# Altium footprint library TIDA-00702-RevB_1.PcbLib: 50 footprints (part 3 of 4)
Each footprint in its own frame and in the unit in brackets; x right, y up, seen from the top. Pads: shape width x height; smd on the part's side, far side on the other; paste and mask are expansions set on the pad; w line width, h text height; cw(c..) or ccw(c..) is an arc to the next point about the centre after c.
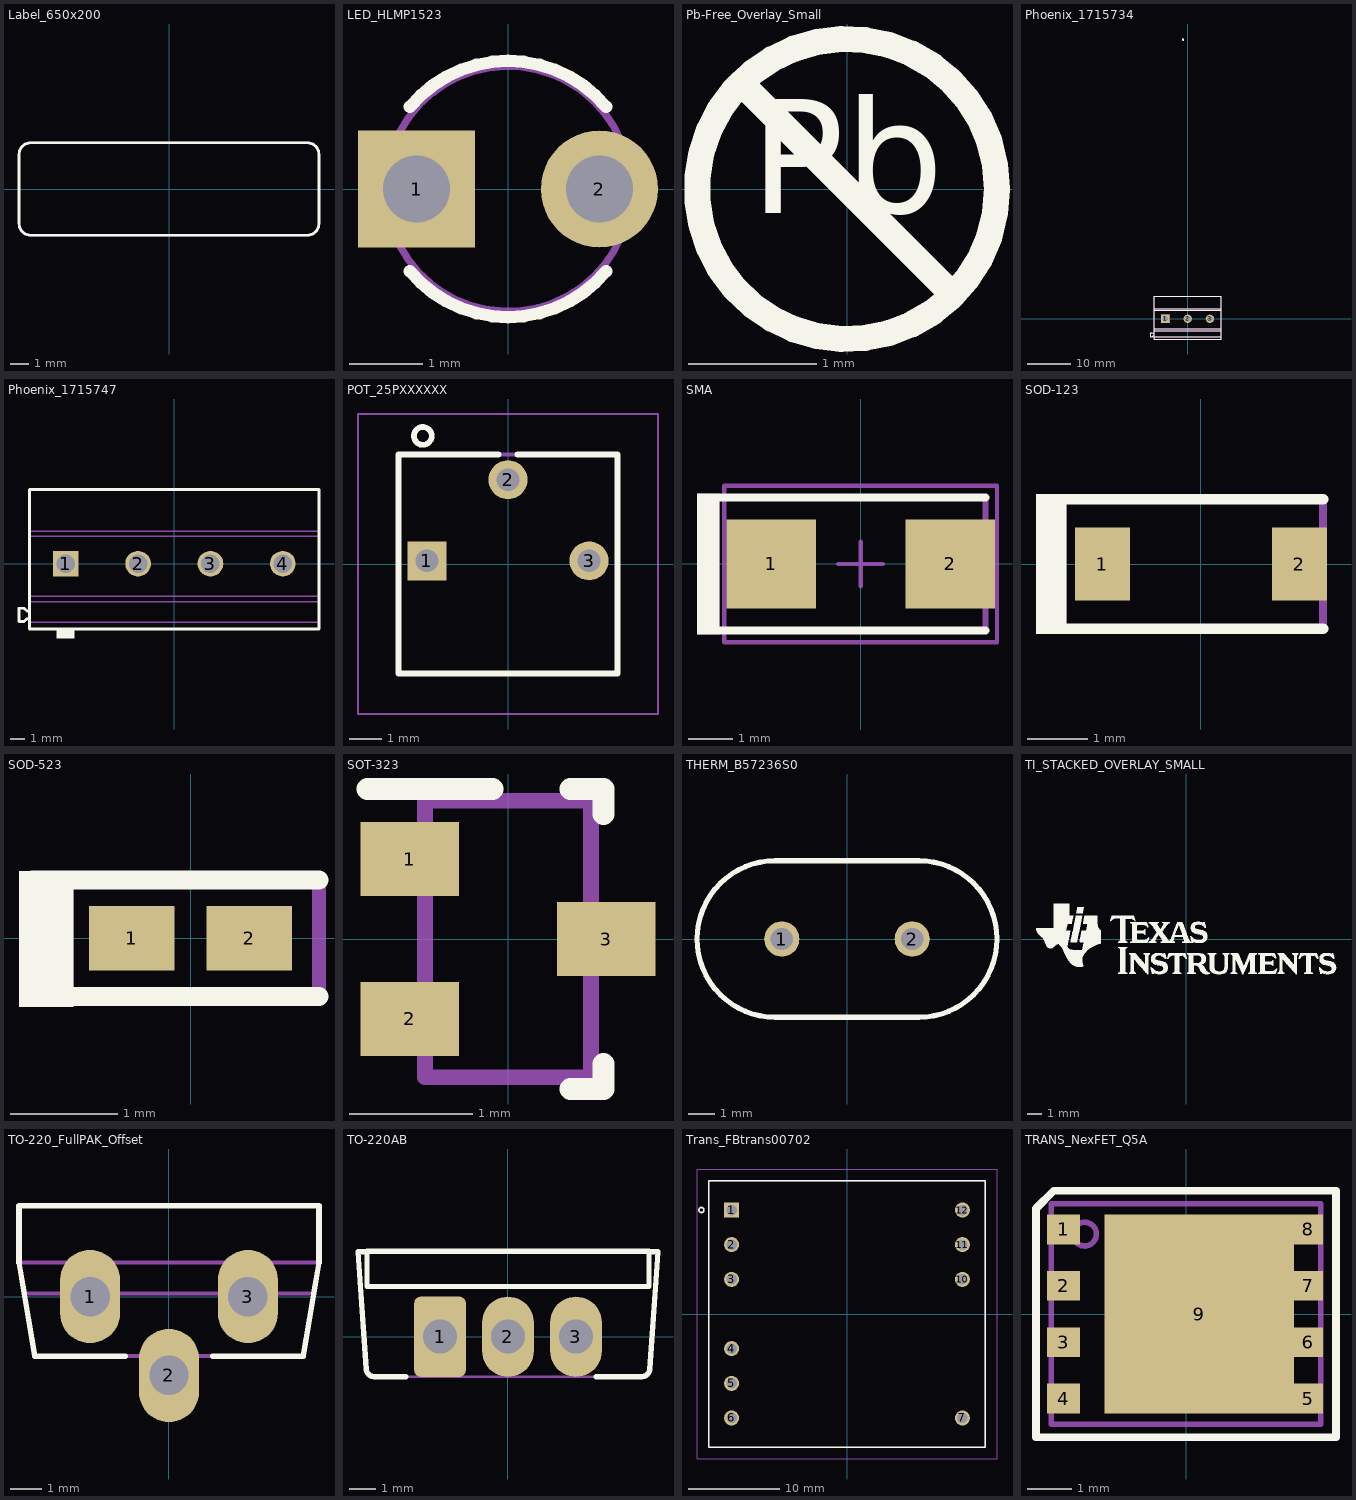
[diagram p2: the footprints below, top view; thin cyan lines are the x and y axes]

## Label_650x200 [mm] "Thermal Transfer Label"
height 0.025
Top Overlay:
  lines w0.152: -8.255,-1.905 ccw(c-7.62,-1.905) -7.62,-2.54 7.62,-2.54 ccw(c7.62,-1.905) 8.255,-1.905 8.255,1.905 ccw(c7.62,1.905) 7.62,2.54 -7.62,2.54 ccw(c-7.62,1.905) -8.255,1.905 -8.255,-1.905
Mechanical 5:
  lines w0.127: -8.255,-1.905 ccw(c-7.62,-1.905) -7.62,-2.54 7.62,-2.54 ccw(c7.62,-1.905) 8.255,-1.905 8.255,1.905 ccw(c7.62,1.905) 7.62,2.54 -7.62,2.54 ccw(c-7.62,1.905) -8.255,1.905 -8.255,-1.905
  text ".Designator" at -1.524,-0.508 h0.89
3D body: height 0.03, standoff 0, extent -8.268,-2.553 8.268,2.553

## LED_HLMP1523 [mm] "Everlight Electronics"
height 4.8
pads (2):
  rect 1.6x1.6 hole 0.914: 1(-1.25,0)
  round 1.6 hole 0.914: 2(1.25,0)
Top Overlay:
  lines w0.17: -1.341,-1.125 ccw(c0,0) 1.341,-1.125 ; -1.341,1.125 cw(c0,0) 1.341,1.125
Mechanical 5:
  lines w0.1: -1.57,-0.571 ccw(c0.004,0.002) -1.57,0.575 -1.57,-0.571
  text ".Designator" at 0.305,-0.635 h0.89
3D body: height 6.2, standoff -4.86, extent -1.6,-1.675 1.675,1.675

## Pb-Free_Overlay_Small [mm]
Top Overlay:
  circle w0.203: c0,0 r1.168
  lines w0.203: -0.826,0.826 0.826,-0.826
  text "Pb" at -0.752,-0.48 h1.52

## Phoenix_1715734 [mm] "Phoenix"
height 13.8
pads (3):
  rect 1.9x1.9 hole 1.321: 1(-5.08,0)
  round 1.9 hole 1.321: 2(0,0) 3(5.08,0)
Top Overlay:
  circle w0.152: c-1.033,63.678 r0.152
  lines w0.2: -7.62,-3.869 -7.787,-3.869 -8.019,-4.064 -8.361,-4.064 -8.361,-3.136 -8.019,-3.136 -7.787,-3.331 -7.62,-3.331 ; -7.62,-4.1 7.62,-4.1 ; -7.62,-4.1 -7.62,-4.6 7.62,-4.6 7.62,-4.1 ; -7.62,-4.1 -7.62,-2.672 ; -7.62,-2.672 7.62,-2.672 ; -7.62,-2.672 -7.62,-2.283 ; -7.62,-2.283 7.62,-2.283 ; -7.62,-2.283 -7.62,1.909 ; -7.62,1.909 7.62,1.909 ; -7.62,1.909 -7.62,2.29 ; -7.62,2.29 7.62,2.29 ; -7.62,2.29 -7.62,5.2 7.62,5.2 7.62,2.29 ; 7.62,-4.1 7.62,-2.672 ; 7.62,-2.672 7.62,-2.283 ; 7.62,-2.283 7.62,1.909 ; 7.62,1.909 7.62,2.29
Mechanical 5:
  region: -6.025,0.95 -4.125,0.95 -4.125,-0.95 -6.025,-0.95
  lines w0.127: -7.62,-3.869 -7.787,-3.869 -8.019,-4.064 -8.361,-4.064 -8.361,-3.136 -8.019,-3.136 -7.787,-3.331 -7.62,-3.331 ; -7.62,-4.1 -7.62,-2.672 ; -7.62,-4.1 -7.62,-4.6 7.62,-4.6 7.62,-4.1 ; -7.62,-4.1 7.62,-4.1 ; -7.62,-2.672 -7.62,-2.283 ; -7.62,-2.672 7.62,-2.672 ; -7.62,-2.283 -7.62,1.909 ; -7.62,-2.283 7.62,-2.283 ; -7.62,1.909 -7.62,2.29 ; -7.62,1.909 7.62,1.909 ; -7.62,2.29 -7.62,5.2 7.62,5.2 7.62,2.29 ; -7.62,2.29 7.62,2.29 ; 7.62,-4.1 7.62,-2.672 ; 7.62,-2.672 7.62,-2.283 ; 7.62,-2.283 7.62,1.909 ; 7.62,1.909 7.62,2.29
  text ".Designator" at -2.21,0.33 h0.89
3D body: height 14.2, standoff -3.5, extent -8.361,-4.6 7.62,5.2

## Phoenix_1715747 [mm] "Terminal Block, 5.08mm, 4x1, TH"
height 13.8
pads (4):
  rect 1.8x1.8 hole 1.3: 1(-7.62,0)
  round 1.8 hole 1.3: 2(-2.54,0) 3(2.54,0) 4(7.62,0)
Top Overlay:
  rectangle: -8.255,-5.25 -7.005,-4.599
  lines w0.2: -10.16,-3.869 -10.327,-3.869 -10.559,-4.064 -10.901,-4.064 -10.901,-3.136 -10.559,-3.136 -10.327,-3.331 -10.16,-3.331 ; -10.16,-4.6 10.16,-4.6 10.16,5.2 -10.16,5.2 -10.16,-4.6
Mechanical 5:
  lines w0.1: -10.16,-4.1 10.16,-4.1 ; -10.16,-3.869 -10.327,-3.869 -10.559,-4.064 -10.901,-4.064 -10.901,-3.136 -10.559,-3.136 -10.327,-3.331 -10.16,-3.331 ; -10.16,-2.672 10.16,-2.672 ; -10.16,-2.283 10.16,-2.283 ; -10.16,1.909 10.16,1.909 ; -10.16,2.29 10.16,2.29 ; -10.16,-4.6 -10.16,5.2 10.16,5.2 10.16,-4.6 -10.16,-4.6
  text ".Designator" at -0.559,0.66 h0.89
3D body: height 14.2, standoff -3.5, extent -10.901,-4.6 10.16,5.2

## POT_25PXXXXXX [mm] "Potentiometer, 25p series, through hole, 3 pin"
height 5.13
pads (3):
  rect 1.222x1.222 hole 0.714: 1(-2.54,0.1)
  round 1.222 hole 0.714: 2(0,2.64) 3(2.54,0.1)
Top Overlay:
  circle w0.178: c-2.667,4.013 r0.279
  lines w0.178: -0.3,3.43 -3.43,3.43 -3.43,-3.43 3.43,-3.43 3.43,3.43 0.3,3.43
  text ".Designator" at 3.708,0.737 h0.89
Mechanical 5:
  circle w0.127: c-2.54,0.1 r0.279
  lines w0.127: -3.43,-3.43 3.43,-3.43 3.43,3.43 -3.43,3.43 -3.43,-3.43
  text ".Designator" at -0.178,1.295 h0.89
Mechanical 15:
  lines w0.05: -4.7,-4.7 4.7,-4.7 4.7,4.7 -4.7,4.7 -4.7,-4.7
Mechanical 17:
  text "Lead Length : 5.08  +/- 1.01mm" at -12.954,1.778 h1.02
3D body: height 5.13, standoff 0, extent -3.43,-3.43 3.43,3.43

## SMA [mm] "Molded Diode, 2-Leads, Body 4.3x2.6mm, IPC Medium Density, based on OnSemi component dimensions and land pattern"
height 2.27
pads (2):
  rect 2x2 smd: 1(-2,0) 2(2,0)
Top Overlay:
  rectangle: -3.658,-1.575 -3.15,1.575
  lines w0.178: -3.327,-1.486 2.794,-1.486 ; -3.327,1.486 2.794,1.486
Mechanical 5:
  rectangle: -3.658,-1.575 -3.15,1.575
  lines w0.127: -3.327,-1.486 2.794,-1.486 2.794,1.486 -3.327,1.486
  text ".Designator" at -2.769,-0.33 h0.89
Mechanical 15:
  lines w0.1: -0.5,0 0.5,0 ; 0,-0.5 0,0.5 ; -3.05,-1.75 3.05,-1.75 3.05,1.75 -3.05,1.75 -3.05,-1.75
3D body: height 2.42, standoff 0.02, extent -2.6,-1.3 2.6,1.3

## SOD-123 [mm] "On Semi recommended land pattern"
height 1.35
pads (2):
  rect 0.915x1.22 smd: 1(-1.637,0) 2(1.637,0)
Top Overlay:
  rectangle: -2.743,-1.168 -2.235,1.168
  lines w0.178: -2.413,-1.079 2.032,-1.079 ; -2.413,1.079 2.032,1.079
Mechanical 5:
  rectangle: -2.743,-1.168 -2.235,1.168
  lines w0.127: -2.413,-1.079 2.032,-1.079 2.032,1.079 -2.413,1.079
  text ".Designator" at -1.956,-0.33 h0.89
3D body: height 1.35, standoff 0, extent -1.932,-0.9 1.932,0.9

## SOD-523 [mm] "NXP Semiconductor recommended land pattern, nominal STEP model"
height 0.7
pads (2):
  rect 0.8x0.6 smd paste-0.05: 1(-0.55,0) 2(0.55,0)
Top Overlay:
  rectangle: -1.602,-0.642 -1.094,0.628
  lines w0.178: -1.475,-0.546 0,-0.546 1.2,-0.546 ; -1.475,0.546 0,0.546 1.2,0.546
Mechanical 5:
  rectangle: -1.602,-0.642 -1.094,0.628
  lines w0.127: -1.475,-0.546 0,-0.546 1.2,-0.546 1.2,0.546 0,0.546 -1.475,0.546
  text ".Designator" at 2.972,0.375 h0.89
3D body: height 0.72, standoff 0.02, extent -0.8,-0.399 0.8,0.399

## SOT-323 [mm] "Zetex recommended land pattern.  March 2007"
height 1.1
pads (3):
  rect 0.8x0.6 smd: 1(-0.8,0.65) 2(-0.8,-0.65) 3(0.8,0)
Top Overlay:
  lines w0.178: -1.143,1.219 -0.127,1.219 ; 0.508,-1.219 0.775,-1.219 0.775,-1.016 ; 0.508,1.219 0.775,1.219 0.775,1.016
Mechanical 5:
  lines w0.127: -1.125,-0.8 -0.975,-0.8 -0.935,-0.8 -0.884,-0.8 -0.725,-0.8 -0.675,-0.8 -0.675,-0.5 -0.725,-0.5 -0.884,-0.5 -0.935,-0.5 -0.975,-0.5 -1.125,-0.5 -1.125,-0.8 ; -1.125,0.5 -0.975,0.5 -0.935,0.5 -0.884,0.5 -0.725,0.5 -0.675,0.5 -0.675,0.8 -0.725,0.8 -0.884,0.8 -0.935,0.8 -0.975,0.8 -1.125,0.8 -1.125,0.5 ; -0.675,-1.125 0.675,-1.125 0.675,1.125 -0.675,1.125 -0.675,-1.125 ; 0.675,-0.15 0.675,0.15 0.725,0.15 0.884,0.15 0.935,0.15 0.975,0.15 1.125,0.15 1.125,-0.15 0.975,-0.15 0.935,-0.15 0.884,-0.15 0.725,-0.15 0.675,-0.15
  text ".Designator" at 0.47,-0.645 h0.89
3D body: height 1.13, standoff 0.02, extent -1.125,-1.125 1.125,1.125

## THERM_B57236S0 [mm] "EPCOS"
height 16
pads (2):
  round 1.35 hole 0.85: 1(-2.5,0) 2(2.5,0)
Top Overlay:
  lines w0.2: -2.75,-3 cw(c-2.75,0) -2.75,3 2.75,3 cw(c2.75,0) 2.75,-3 -2.75,-3
Mechanical 5:
  lines w0.1: -2.75,-3 cw(c-2.75,0) -2.75,3 2.75,3 cw(c2.75,0) 2.75,-3 -2.75,-3
  text ".Designator" at -0.864,0.178 h0.89
3D body: height 15.99, standoff 4.51, extent -5.755,-3 5.7,3
3D body: height 5.5, standoff -2.5, extent 2.202,-0.299 2.8,0.3
3D body: height 5.5, standoff -2.5, extent -2.797,-0.299 -2.2,0.3

## TI_STACKED_OVERLAY_SMALL [mm]
Top Overlay:
  drawing of 18 lines, arcs and shapes, not listed

## TO-220_FullPAK_Offset [mm] "Infineon  PG-TO220-3-31"
height 19.4
pads (3):
  oval 1.93x3 hole 1.27: 1(-2.54,0) 2(0,-2.54) 3(2.54,0)
Top Overlay:
  lines w0.178: -4.655,0.095 -4.825,1.095 ; -4.325,-1.915 -1.4,-1.915 ; -4.325,-1.915 -4.825,1.085 -4.825,1.095 ; 1.4,-1.915 4.325,-1.915 4.825,1.085 4.825,1.095 ; 4.655,0.095 4.825,1.095 ; -4.825,1.095 -4.825,2.915 4.825,2.915 4.825,1.095
Mechanical 5:
  lines w0.127: -0.89,-1.915 -0.89,-2.058 -0.89,-2.853 0.89,-2.853 0.89,-1.915 ; -4.825,1.095 -4.655,0.095 4.655,0.095 4.825,1.095 ; -4.825,1.095 4.825,1.095 ; -4.825,1.095 -4.825,2.915 4.825,2.915 4.825,1.095 ; -4.825,1.095 -4.825,1.085 -4.325,-1.915 4.325,-1.915 4.825,1.085 4.825,1.095
  text ".Designator" at -0.635,-0.203 h0.89
3D body: height 22.91, standoff -3.95, extent -4.825,-2.845 4.825,2.915

## TO-220AB [mm] "Copied from Altium's version of TO3B"
height 19.4
pads (3):
  rrect25% 1.93x3 hole 1.27: 1(-2.54,0)
  oval 1.93x3 hole 1.27: 2(0,0) 3(2.54,0)
Top Overlay:
  lines w0.2: -5.27,3.175 -5.606,3.175 ; -5.27,3.185 -5.606,3.185 -5.606,3.175 ; -3.81,-1.495 -5,-1.495 cw(c-5,-1.195) -5.297,-1.237 cw(c-5,-1.195) -5.299,-1.216 -5.606,3.175 ; 3.302,-1.495 5,-1.495 ccw(c5,-1.195) 5.297,-1.237 ccw(c5,-1.195) 5.3,-1.216 5.607,3.175 ; 5.27,3.175 5.607,3.175 ; 5.27,3.185 5.607,3.185 5.607,3.175 ; -5.27,1.875 5.27,1.875 5.27,3.195 -5.27,3.195 -5.27,1.875
Mechanical 5:
  lines w0.1: -5.27,3.175 -5.606,3.175 ; -5.27,3.185 -5.606,3.185 -5.606,3.175 ; 5.27,3.175 5.607,3.175 ; 5.27,3.185 5.607,3.185 5.607,3.175 ; -5.606,3.175 -5.299,-1.216 ccw(c-5,-1.195) -5.297,-1.237 ccw(c-5,-1.195) -5,-1.495 5,-1.495 ccw(c5,-1.195) 5.297,-1.237 ccw(c5,-1.195) 5.3,-1.216 5.607,3.175 ; -5.27,1.875 -5.27,3.195 5.27,3.195 5.27,1.875 -5.27,1.875
  text ".Designator" at -1.524,-0.508 h0.89
3D body: height 19.42, standoff -3.88, extent -5.606,-1.495 5.607,3.195

## Trans_FBtrans00702 [mm] "TRANSFORMER, VERTICAL, THT, 12-PIN"
height 29.3
pads (12):
  rect 1.65x1.65 / inner round 1.65 / far side rect 1.65x1.65 hole 1.15: 1(-12.65,11.4)
  round 1.65 hole 1.15: 2(-12.65,7.6) 3(-12.65,3.8) 4(-12.65,-3.8) 5(-12.65,-7.6) 6(-12.65,-11.4) 7(12.65,-11.4) 10(12.65,3.8) 11(12.65,7.6) 12(12.65,11.4)
  round 0 all layers, no hole: 8(12.65,-7.6) 9(12.65,-3.8)
Top Overlay:
  circle w0.178: c-15.964,11.4 r0.279
  lines w0.178: -15.175,-14.6 15.175,-14.6 15.175,14.6 -15.175,14.6 -15.175,-14.6
Mechanical 5:
  circle w0.127: c-12.649,11.405 r0.279
  lines w0.127: -15.175,-14.6 15.175,-14.6 15.175,14.6 -15.175,14.6 -15.175,-14.6
  text ".Designator" at -1.524,-0.508 h0.89
Mechanical 15:
  lines w0.05: -16.445,-15.87 16.445,-15.87 16.445,15.87 -16.445,15.87 -16.445,-15.87
Mechanical 17:
  text "LEAD LENGTH IS 3.75MM" at -14.605,-18.796 h1.52
3D body: height 29.3, standoff 0, extent -15.24,-14.605 15.24,14.605

## TRANS_NexFET_Q5A [mm] "TI recommended land pattern (nominal) M0139-01"
height 1.1
pads (9):
  rect 0.75x0.675 smd paste-0.1: 1(-2.776,1.917) 2(-2.776,0.639) 3(-2.776,-0.639) 4(-2.776,-1.917)
  rect 0.655x0.675 smd paste-0.1: 5(2.776,-1.917) 6(2.776,-0.639) 7(2.776,0.639) 8(2.776,1.917)
  rect 4.295x4.51 smd paste-2.2: 9(0.301,0)
Top Overlay:
  lines w0.178: -3.4,-2.795 -3.4,0 -3.4,2.39 -2.995,2.795 0,2.795 3.4,2.795 3.4,0 3.4,-2.795 0,-2.795 -3.4,-2.795
Top Paste:
  region: -1.412,-0.31 -1.412,-1.88 -0.177,-1.88 -0.177,-0.31
  region: -1.412,0.31 -1.412,1.88 -0.177,1.88 -0.177,0.31
  region: 0.323,-0.31 0.323,-1.88 1.908,-1.88 1.908,-0.31
  region: 0.323,0.31 0.323,1.88 1.908,1.88 1.908,0.31
Mechanical 5:
  circle w0.127: c-2.3,1.81 r0.269
  lines w0.127: -3.05,-2.5 -3.05,2.5 3.05,2.5 3.05,-2.5 -3.05,-2.5
  text ".Designator" at 0.533,-0.838 h0.89
3D body: height 1.11, standoff 0, extent -3.05,-2.5 3.05,2.5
